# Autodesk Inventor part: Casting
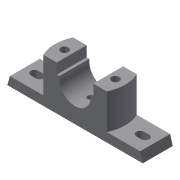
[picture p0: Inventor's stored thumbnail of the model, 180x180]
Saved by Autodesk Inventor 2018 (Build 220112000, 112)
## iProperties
Created: 2009-04
Part Number: Casting
Document SubType Name: Modeling
Designer: Sham
Density: 1 g/cm^3
Material: Generic
Appearance: Default
Author: Sham
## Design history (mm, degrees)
sketch "Sketch1"
  geometry: L1 (-104, 0)-(104, 0); L2 (-104, 0)-(-100, 14); L3 (-100, 14)-(100, 14); L4 (100, 14)-(104, 0); 1 further point
  constraints: 8 end point, 1 horizontal, 1 midpoint, 1 parallel, 1 other
  dimensions: "d0" = 208 distance of L1.start L1.end; "d1" = 104 distance of L1.end point (0, 0); "d2" = 4 horizontal distance of L1.start L2.end; "d3" = 4 horizontal distance of L1.end L3.end; "d10" = 14 distance between parallel lines of L1 L3
extrude "Extrusion1" new body sketch "Sketch1" stored distance "d4" = 46; taper "d5" = 0 deg
sketch "Sketch2"
  geometry: L1 (51.143, 46)-(148.857, 46); L2 (148.857, 0)-(51.143, 0); A1 r 54 centre (100, 23) between (51.143, 46) and (51.143, 0); A2 r 54 centre (100, 23) between (148.857, 0) and (148.857, 46)
  constraints: 4 end point, 4 point on circle, 2 centre point, 1 parallel
extrude "Extrusion2" join sketch "Sketch2" distance "d8" = 54; taper "d9" = 0 deg
sketch "Sketch3"
  geometry: L1 (-28, 68)-(-28, 52); L2 (-28, 52)-(-24, 52); L3 (28, 68)-(28, 52); L4 (28, 52)-(24, 52); L5 (-28, 68)-(28, 68); L6 (-100, 14)-(-48.857, 14) reference; L7 (0, 48)-(0, 19); L8 (48.857, 14)-(100, 14) reference; L9 (48.857, 68)-(-48.857, 68) reference; L10 (-24, 48)-(-24, 52); L11 (24, 48)-(24, 52); A1 r 24 centre (0, 48) between (-24, 48) and (24, 48); 1 further point
  constraints: 16 end point, 5 perpendicular, 2 point on circle, 2 symmetric about line, 1 centre point, 1 tangent, 1 vertical alignment, 1 other
  dimensions: "d11" = 16 distance of L1.start L1.end; "d16" = 24 radius of A1; "d17" = 16 distance of L3.start L3.end; "d52" = 56 distance between parallel lines of L1 L3; "d54" = 54 distance between parallel lines of L8 L9 (derived)
extrude "Extrusion3" cut sketch "Sketch3" distance "d18" = 54; taper "d19" = 0 deg
sketch "Sketch4"
  geometry: L1 (-23, 29)-(-15, 29); L2 (-15, 17)-(-23, 17); L3 (-185, 29)-(-177, 29); L4 (-177, 17)-(-185, 17); A1 r 6 centre (-15, 23) between (-15, 17) and (-15, 29); A2 r 6 centre (-23, 23) between (-23, 29) and (-23, 17); A3 r 6 centre (-177, 23) between (-177, 17) and (-177, 29); A4 r 6 centre (-185, 23) between (-185, 29) and (-185, 17)
  constraints: 8 end point, 8 point on circle, 8 tangent, 4 centre point, 3 parallel
  dimensions: "d20" = 8 distance of A1.centre A2.centre; "d21" = 6 radius of A1; "d24" = 6 radius of A3; "d25" = 8 distance of A4.centre A3.centre
extrude "Extrusion4" cut sketch "Sketch4" distance "d28" = 54; taper "d29" = 0 deg
sketch "Sketch5"
  geometry: L1 (208, 0)-(0, 0) reference; L2 (52, -10)-(78, -10); L3 (78, -10)-(78, -36); L4 (78, -36)-(52, -36); L5 (52, -36)-(52, -10); L6 (130, -10)-(156, -10); L7 (156, -10)-(156, -36); L8 (156, -36)-(130, -36); L9 (130, -36)-(130, -10); L10 (0, -46)-(208, -46) reference; L11 (104, -23)-(104, -46)
  constraints: 18 end point, 5 perpendicular, 4 parallel, 2 horizontal, 1 midpoint
  dimensions: "d30" = 26 distance of L2.start L2.end; "d31" = 10 distance between parallel lines of L2 L1; "d32" = 10 distance between parallel lines of L1 L6; "d65" = 26 distance between parallel lines of L3 L11; "d66" = 26 distance between parallel lines of L9 L11
extrude "Extrusion5" cut sketch "Sketch5" distance "d34" = 10; taper "d35" = 0 deg
sketch "Sketch6"
  geometry: L1 (148.857, 0)-(128, 0) reference; L2 (72, 0)-(51.143, 0) reference; L3 (0, 46)-(0, 0) reference; L4 (200, 46)-(200, 0) reference; C1 r 6 at (61, 23); C2 r 6 at (139, 23); 1 further point
  constraints: 2 centre point, 1 equal radius
  dimensions: "d36" = 12 diameter of C1; "d37" = 78 distance of C2.centre C1.centre; "d39" = 39 distance of C2.centre point (100, 23); "d58" = 39 distance of C1.centre point (100, 23); "d59" = 23 distance from line of L1 C2.centre; "d60" = 23 distance from line of L2 C1.centre; "d61" = 61 distance from line of L3 C1.centre; "d62" = 61 distance from line of L4 C2.centre (derived)
extrude "Extrusion6" cut sketch "Sketch6" extent not by distance; stored distance "d40" = 10; taper "d41" = 0 deg
workplane "Work Plane1"
sketch "Sketch7"
  geometry: L1 (-4, 46)-(204, 46) reference; L2 (-4, 0)-(-4, 46) reference; 1 further point
  dimensions: "d43" = 23 distance from line of L1 point (100, 23); "d44" = 104 distance from line of point (100, 23) L2
hole "Hole1" sketch "Sketch7" at (100, 23) diameter "d45" = 8; stored, may be unused: countersink angle "d49" = 90 deg, drill point angle "d51" = 118 deg; dims "d46" = 6, "d47" = 8, "d48" = 16, "d50" = 8
body "Solid1"
other parameters: "d6" = 108, "d42" = -52
